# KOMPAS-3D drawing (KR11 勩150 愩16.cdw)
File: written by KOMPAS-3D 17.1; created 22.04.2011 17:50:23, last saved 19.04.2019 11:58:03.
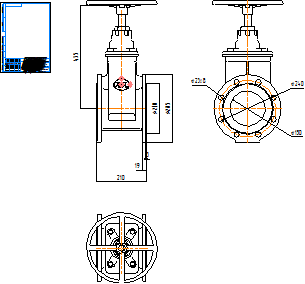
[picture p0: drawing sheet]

Title block, sheet 1: name: KR11 Ду150 Ру16; material: Внимание! Данный продукт является объектом авторского права ООО «Торговый Дом АДЛ». / Запрещается изменение, копирование, распространение / (в том числе путем копирования на другие сайты и ресурсы в Интернете) / или любое иное использование информации и объектов без предварительного / согласия правообладателя (ООО «Торговый Дом АДЛ»).; scale: 1:1; sheets: 1; organisation: ООО "Торговый дом АДЛ"; sheet format: A4; stored path: \\adlc.lan\data\АДЛ_ПКД\3D-модели\ADL production\Клиновые задвижки серии KR ГРАНАР\Клиновые задвижки KR11\KOMPAS 2D\KR11 Ду150 Ру16.cdw

Views: Спереди 7, Проекционный вид 8, Проекционный вид 9
Dimensions and other numbers on the sheet: 285; 210; 435; 19; 3; 23; 240; 150; 1:1; 1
